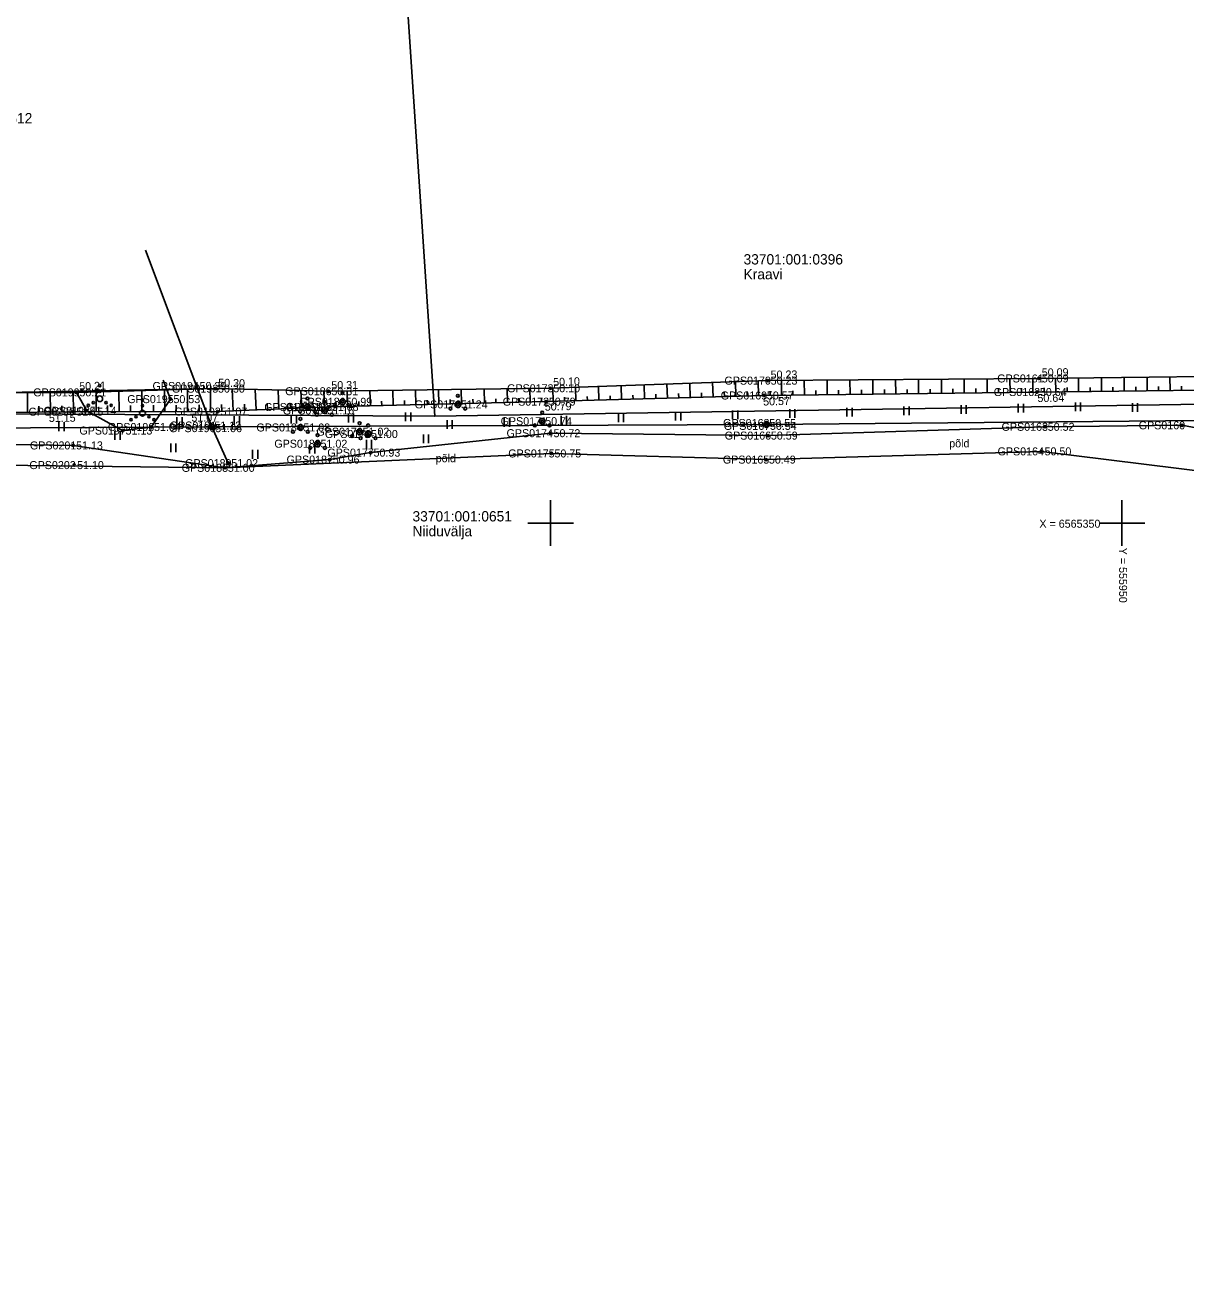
# Model space of a CAD drawing. Extents: x 551623 to 559850, y 6561220 to 6567135.
# Drawn here: x 555854 to 555955.5, y 6565284.2 to 6565393.6 of the extents above; entities that cross this region are included whole.
import ezdxf

# ---------------------------------------------------------------- set-up
doc = ezdxf.new("R2010")
doc.units = 0
for name, color, linetype in [('HALJASTUS', 7, 'Continuous'), ('KORGUS-EH2000', 7, 'Continuous'), ('KPOHULIIN', 7, 'Continuous'), ('MOOTKORG-EH2000', 7, 'Continuous'), ('MOOTMPUNKT', 7, 'Continuous'), ('MOOTNR', 7, 'Continuous'), ('MOOTPIIR', 7, 'Continuous'), ('MPOHULIIN', 7, 'Continuous'), ('PIIR', 7, 'Continuous'), ('POST', 7, 'Continuous'), ('PUU', 7, 'Continuous'), ('RELJEEF', 7, 'Continuous'), ('VORK', 7, 'Continuous')]:
    doc.layers.add(name, color=color, linetype=linetype)

msp = doc.modelspace()

# ---------------------------------------------------------------- linework, layer by layer
at = {"layer": 'HALJASTUS'}
for p, q in [((555930.93, 6565360.19), (555930.93, 6565359.43)), ((555931.39, 6565360.19), (555931.39, 6565359.43)), ((555935.93, 6565360.31), (555935.93, 6565359.55)), ((555936.38, 6565360.31), (555936.38, 6565359.55)), ((555940.93, 6565360.43), (555940.93, 6565359.67)), ((555941.38, 6565360.43), (555941.38, 6565359.67)), ((555945.93, 6565360.55), (555945.93, 6565359.78)), ((555946.38, 6565360.55), (555946.38, 6565359.78)), ((555950.92, 6565360.5), (555950.92, 6565359.74)), ((555951.37, 6565360.5), (555951.37, 6565359.74)), ((555867.31, 6565359.25), (555867.31, 6565358.49)), ((555867.77, 6565359.25), (555867.77, 6565358.49)), ((555872.31, 6565359.35), (555872.31, 6565358.59)), ((555872.77, 6565359.35), (555872.77, 6565358.59)), ((555877.31, 6565359.46), (555877.31, 6565358.7)), ((555877.77, 6565359.46), (555877.77, 6565358.7)), ((555882.31, 6565359.57), (555882.31, 6565358.8)), ((555882.76, 6565359.57), (555882.76, 6565358.8)), ((555887.31, 6565359.67), (555887.31, 6565358.91)), ((555887.76, 6565359.67), (555887.76, 6565358.91)), ((555895.95, 6565359.19), (555895.95, 6565358.43)), ((555896.4, 6565359.19), (555896.4, 6565358.43)), ((555900.94, 6565359.39), (555900.94, 6565358.63)), ((555901.4, 6565359.39), (555901.4, 6565358.63)), ((555905.94, 6565359.58), (555905.94, 6565358.82)), ((555906.39, 6565359.58), (555906.39, 6565358.82)), ((555910.94, 6565359.72), (555910.94, 6565358.96)), ((555911.39, 6565359.72), (555911.39, 6565358.96)), ((555915.93, 6565359.84), (555915.93, 6565359.08)), ((555916.39, 6565359.84), (555916.39, 6565359.08)), ((555920.93, 6565359.96), (555920.93, 6565359.19)), ((555921.39, 6565359.96), (555921.39, 6565359.19)), ((555925.93, 6565360.07), (555925.93, 6565359.31)), ((555926.39, 6565360.07), (555926.39, 6565359.31)), ((555856.97, 6565358.82), (555856.97, 6565358.05)), ((555857.43, 6565358.82), (555857.43, 6565358.05)), ((555861.88, 6565358.03), (555861.88, 6565357.27)), ((555862.33, 6565358.03), (555862.33, 6565357.27)), ((555890.95, 6565359), (555890.95, 6565358.23)), ((555891.4, 6565359), (555891.4, 6565358.23)), ((555866.76, 6565356.97), (555866.76, 6565356.2)), ((555867.21, 6565356.97), (555867.21, 6565356.2)), ((555878.91, 6565356.84), (555878.91, 6565356.08)), ((555879.36, 6565356.84), (555879.36, 6565356.08)), ((555883.89, 6565357.29), (555883.89, 6565356.53)), ((555884.34, 6565357.29), (555884.34, 6565356.53)), ((555888.87, 6565357.75), (555888.87, 6565356.98)), ((555889.32, 6565357.75), (555889.32, 6565356.98)), ((555873.93, 6565356.39), (555873.93, 6565355.63)), ((555874.38, 6565356.39), (555874.38, 6565355.63))]:
    msp.add_line(p, q, dxfattribs=at)
for points in [[(555858.51, 6565361.42), (555859.41, 6565359.82), (555862.55, 6565358.09), (555865.04, 6565358.4), (555866.74, 6565360.84), (555866.1, 6565362.51)], [(555785.42, 6565354.5), (555797.66, 6565356.6), (555822.01, 6565356.17), (555839.03, 6565357.1), (555858.22, 6565356.79), (555871.5, 6565354.83), (555880.68, 6565355.55), (555884.25, 6565356.16), (555900, 6565357.86), (555919.02, 6565357.65), (555943.25, 6565358.42), (555955.25, 6565358.55), (555967.13, 6565356.34), (555981.6, 6565352.01), (555991.48, 6565347.29)]]:
    msp.add_lwpolyline(points, dxfattribs=at)
for centre, radius in [((555860.55, 6565362.02), 0.1), ((555860.55, 6565361.52), 0.1), ((555859.55, 6565360.29), 0.1), ((555859.98, 6565360.54), 0.1), ((555860.55, 6565360.87), 0.25), ((555861.11, 6565360.54), 0.1), ((555861.55, 6565360.29), 0.1), ((555864.29, 6565360.76), 0.1), ((555864.29, 6565360.26), 0.1), ((555863.29, 6565359.04), 0.1), ((555863.73, 6565359.29), 0.1), ((555864.29, 6565359.61), 0.25), ((555864.86, 6565359.29), 0.1), ((555865.29, 6565359.04), 0.1)]:
    msp.add_circle(centre, radius, dxfattribs=at)
at = {"layer": 'KORGUS-EH2000'}
for centre in [(555919, 6565362.46), (555942.73, 6565362.65), (555858.51, 6565361.42), (555870.64, 6565361.76), (555880.56, 6565361.53), (555899.98, 6565361.79), (555918.67, 6565361.16), (555942.56, 6565361.46), (555880.6, 6565360.16), (555899.59, 6565360.62), (555858.24, 6565359.74), (555870.86, 6565359.75), (555943.25, 6565358.42), (555955.25, 6565358.55), (555858.22, 6565356.79), (555919.02, 6565357.65), (555884.25, 6565356.16), (555900.08, 6565356.09), (555942.97, 6565356.27), (555858.31, 6565355.07), (555871.5, 6565354.83), (555880.68, 6565355.55), (555918.85, 6565355.55)]:
    msp.add_circle(centre, 0.1, dxfattribs=at)
at = {"layer": 'KPOHULIIN'}
msp.add_lwpolyline([(555766.29, 6565358.13), (555774.48, 6565357.81), (555774.48, 6565357.81), (555822.76, 6565358.14), (555870.36, 6565358.42), (555918.91, 6565358.62), (555918.91, 6565358.62), (555966.51, 6565359.06), (556012.01, 6565359.61), (556063.1, 6565345.17), (556063.1, 6565345.17), (556112.63, 6565331.11), (556160.57, 6565309.95), (556211.02, 6565287.53)], dxfattribs=at)
at = {"layer": 'MOOTMPUNKT'}
for centre in [(555919, 6565362.46), (555942.73, 6565362.65), (555858.51, 6565361.42), (555869.02, 6565361.99), (555870.64, 6565361.76), (555880.56, 6565361.53), (555899.98, 6565361.79), (555918.67, 6565361.16), (555942.56, 6565361.46), (555866.74, 6565360.84), (555878.73, 6565360.15), (555880.6, 6565360.16), (555881.79, 6565360.61), (555891.89, 6565360.38), (555899.59, 6565360.62), (555858.24, 6565359.74), (555859.41, 6565359.82), (555870.86, 6565359.75), (555880.21, 6565359.85), (555862.55, 6565358.09), (555865.04, 6565358.4), (555870.32, 6565358.53), (555870.4, 6565358.3), (555878.11, 6565358.36), (555883.29, 6565357.99), (555899.27, 6565358.91), (555900, 6565357.86), (555918.88, 6565358.75), (555918.94, 6565358.5), (555943.25, 6565358.42), (555955.25, 6565358.55), (555858.22, 6565356.79), (555879.61, 6565356.94), (555884.03, 6565357.79), (555919.02, 6565357.65), (555884.25, 6565356.16), (555900.08, 6565356.09), (555942.97, 6565356.27), (555858.31, 6565355.07), (555871.5, 6565354.83), (555871.8, 6565355.24), (555880.68, 6565355.55), (555918.85, 6565355.55)]:
    msp.add_circle(centre, 0.1, dxfattribs=at)
at = {"layer": 'MOOTPIIR'}
for points in [[(556057.93, 6565353.82), (556039.2, 6565356.19), (556028.75, 6565357.94), (556026.17, 6565358.36), (556019.77, 6565359.21), (556019.9, 6565364.75), (556021.56, 6565374.26), (556015.15, 6565374.33), (556012.73, 6565375.39), (555993.91, 6565375.82), (555986.51, 6565374.87), (555981.26, 6565364.2), (555966.86, 6565362.93), (555942.73, 6565362.65), (555919, 6565362.46), (555899.98, 6565361.79), (555880.56, 6565361.53), (555870.64, 6565361.76), (555852.22, 6565361.42)], [(555839.44, 6565355.22), (555871.5, 6565354.83), (555900.08, 6565356.09), (555918.85, 6565355.55), (555942.97, 6565356.27), (555966.76, 6565353.3), (555985.37, 6565350.61), (555996.73, 6565349.22), (556009.02, 6565348.03), (556019.67, 6565346.94), (556026.62, 6565346.44), (556031.51, 6565345.23), (556038.74, 6565344.78), (556063.16, 6565343.59)]]:
    msp.add_lwpolyline(points, dxfattribs=at)
at = {"layer": 'MPOHULIIN'}
for points in [[(555864.55, 6565373.87), (555870.36, 6565358.42)], [(555774.48, 6565357.81), (555822.76, 6565358.14), (555822.76, 6565358.14), (555870.36, 6565358.42)]]:
    msp.add_lwpolyline(points, dxfattribs=at)
at = {"layer": 'PIIR'}
for points in [[(555860.69, 6565787.05), (556134.83, 6565867.67), (556136.76, 6565868.24), (556138.68, 6565868.81), (556304.72, 6565917.64), (556407.28, 6565947.65), (556409.2, 6565948.21), (556411.12, 6565948.77), (556555.39, 6565990.98), (556602.55, 6565855.41), (556340.11, 6565662.55), (556145.23, 6565518.55), (556122.95, 6565328.71), (556065.95, 6565349.3), (555986.85, 6565360.88), (555889.86, 6565359.34), (555877.35, 6565546.73)], [(555823.05, 6565554.69), (555877.35, 6565546.73), (555889.86, 6565359.34), (555792.17, 6565359.86)], [(555766.77, 6565362.31), (555785.15, 6565359.9), (555792.17, 6565359.86), (555889.86, 6565359.34), (555986.85, 6565360.88), (556065.95, 6565349.3), (556122.95, 6565328.71), (556199.38, 6565295.85), (556198.85, 6565282.81), (556195.83, 6565275.41), (556189.32, 6565262.35), (556176.88, 6565235.57), (556133.25, 6565139.15), (556097.67, 6565060.64), (555982.17, 6564796.57), (555965.54, 6564731.83), (555935.2, 6564801.96), (555871.92, 6565015.39), (555870.22, 6565021.13), (555867.36, 6565030.76)]]:
    msp.add_lwpolyline(points, close=True, dxfattribs=at)
at = {"layer": 'POST'}
msp.add_lwpolyline([(555870.36, 6565358.42), (555871.8, 6565355.24)], dxfattribs=at)
for centre, radius in [((555870.36, 6565358.42), 0.25), ((555918.91, 6565358.62), 0.25), ((555871.8, 6565355.24), 0.125), ((555871.8, 6565355.24), 0.105), ((555871.8, 6565355.24), 0.0851), ((555871.8, 6565355.24), 0.0651), ((555871.8, 6565355.24), 0.0451), ((555871.8, 6565355.24), 0.0251), ((555871.8, 6565355.24), 0.00511)]:
    msp.add_circle(centre, radius, dxfattribs=at)
at = {"layer": 'PUU'}
for centre, radius in [((555881.79, 6565361.36), 0.125), ((555891.89, 6565361.13), 0.125), ((555878.73, 6565360.15), 0.25), ((555878.73, 6565360.9), 0.125), ((555880.21, 6565360.6), 0.125), ((555881.14, 6565360.23), 0.125), ((555881.79, 6565360.61), 0.25), ((555882.44, 6565360.23), 0.125), ((555891.24, 6565360.01), 0.125), ((555891.89, 6565360.38), 0.25), ((555892.54, 6565360.01), 0.125), ((555878.08, 6565359.78), 0.125), ((555878.11, 6565359.11), 0.125), ((555879.38, 6565359.78), 0.125), ((555879.56, 6565359.48), 0.125), ((555880.21, 6565359.85), 0.25), ((555880.86, 6565359.48), 0.125), ((555899.27, 6565358.91), 0.25), ((555899.27, 6565359.66), 0.125), ((555877.46, 6565357.99), 0.125), ((555878.11, 6565358.36), 0.25), ((555878.76, 6565357.99), 0.125), ((555883.29, 6565357.99), 0.25), ((555883.29, 6565358.74), 0.125), ((555884.03, 6565357.79), 0.25), ((555884.03, 6565358.54), 0.125), ((555898.62, 6565358.54), 0.125), ((555899.92, 6565358.54), 0.125), ((555879.61, 6565356.94), 0.25), ((555879.61, 6565357.69), 0.125), ((555882.64, 6565357.61), 0.125), ((555883.38, 6565357.42), 0.125), ((555883.94, 6565357.61), 0.125), ((555884.68, 6565357.42), 0.125), ((555878.96, 6565356.57), 0.125), ((555880.26, 6565356.57), 0.125)]:
    msp.add_circle(centre, radius, dxfattribs=at)
at = {"layer": 'RELJEEF'}
for p, q in [((555916.21, 6565361.09), (555916.18, 6565362.36)), ((555918.21, 6565361.14), (555918.18, 6565362.43)), ((555920.21, 6565361.18), (555920.2, 6565362.47)), ((555922.21, 6565361.2), (555922.2, 6565362.48)), ((555924.21, 6565361.23), (555924.2, 6565362.5)), ((555926.21, 6565361.25), (555926.2, 6565362.52)), ((555928.21, 6565361.28), (555928.2, 6565362.53)), ((555930.21, 6565361.3), (555930.2, 6565362.55)), ((555932.21, 6565361.33), (555932.2, 6565362.56)), ((555934.21, 6565361.35), (555934.2, 6565362.58)), ((555936.21, 6565361.38), (555936.2, 6565362.59)), ((555938.21, 6565361.41), (555938.2, 6565362.61)), ((555940.21, 6565361.43), (555940.2, 6565362.63)), ((555942.21, 6565361.46), (555942.2, 6565362.64)), ((555944.21, 6565361.48), (555944.2, 6565362.66)), ((555946.21, 6565361.5), (555946.2, 6565362.69)), ((555948.21, 6565361.53), (555948.2, 6565362.71)), ((555950.21, 6565361.55), (555950.2, 6565362.73)), ((555952.21, 6565361.57), (555952.2, 6565362.76)), ((555954.21, 6565361.6), (555954.2, 6565362.78)), ((555854.24, 6565359.7), (555854.22, 6565361.42)), ((555856.24, 6565359.72), (555856.22, 6565361.42)), ((555858.24, 6565359.74), (555858.22, 6565361.42)), ((555860.24, 6565359.74), (555860.23, 6565361.47)), ((555862.24, 6565359.74), (555862.23, 6565361.53)), ((555864.24, 6565359.74), (555864.23, 6565361.59)), ((555866.24, 6565359.74), (555866.23, 6565361.64)), ((555868.24, 6565359.74), (555868.23, 6565361.7)), ((555870.24, 6565359.75), (555870.23, 6565361.75)), ((555872.23, 6565359.81), (555872.15, 6565361.73)), ((555874.23, 6565359.89), (555874.16, 6565361.68)), ((555876.23, 6565359.98), (555876.16, 6565361.63)), ((555878.23, 6565360.06), (555878.16, 6565361.58)), ((555880.23, 6565360.15), (555880.17, 6565361.54)), ((555882.23, 6565360.2), (555882.19, 6565361.55)), ((555884.23, 6565360.25), (555884.19, 6565361.58)), ((555886.22, 6565360.3), (555886.19, 6565361.6)), ((555888.22, 6565360.35), (555888.19, 6565361.63)), ((555890.22, 6565360.4), (555890.19, 6565361.66)), ((555892.22, 6565360.45), (555892.19, 6565361.69)), ((555894.22, 6565360.49), (555894.19, 6565361.71)), ((555896.22, 6565360.54), (555896.19, 6565361.74)), ((555898.22, 6565360.59), (555898.19, 6565361.77)), ((555900.22, 6565360.64), (555900.19, 6565361.8)), ((555902.22, 6565360.7), (555902.19, 6565361.87)), ((555904.22, 6565360.75), (555904.19, 6565361.94)), ((555906.22, 6565360.81), (555906.18, 6565362.01)), ((555908.22, 6565360.86), (555908.18, 6565362.08)), ((555909.22, 6565360.89), (555909.21, 6565361.26)), ((555910.22, 6565360.92), (555910.18, 6565362.15)), ((555911.22, 6565360.95), (555911.21, 6565361.32)), ((555912.22, 6565360.98), (555912.18, 6565362.22)), ((555913.22, 6565361), (555913.21, 6565361.38)), ((555914.22, 6565361.03), (555914.18, 6565362.29)), ((555915.21, 6565361.06), (555915.2, 6565361.44)), ((555917.21, 6565361.12), (555917.2, 6565361.5)), ((555919.21, 6565361.16), (555919.21, 6565361.55)), ((555921.21, 6565361.19), (555921.21, 6565361.58)), ((555923.21, 6565361.22), (555923.21, 6565361.6)), ((555925.21, 6565361.24), (555925.21, 6565361.62)), ((555927.21, 6565361.27), (555927.21, 6565361.64)), ((555929.21, 6565361.29), (555929.21, 6565361.67)), ((555931.21, 6565361.32), (555931.21, 6565361.69)), ((555933.21, 6565361.34), (555933.21, 6565361.71)), ((555935.21, 6565361.37), (555935.21, 6565361.73)), ((555937.21, 6565361.39), (555937.21, 6565361.76)), ((555939.21, 6565361.42), (555939.21, 6565361.78)), ((555941.21, 6565361.44), (555941.21, 6565361.8)), ((555943.21, 6565361.47), (555943.21, 6565361.82)), ((555945.21, 6565361.49), (555945.21, 6565361.85)), ((555947.21, 6565361.52), (555947.21, 6565361.87)), ((555949.21, 6565361.54), (555949.21, 6565361.89)), ((555951.21, 6565361.56), (555951.21, 6565361.92)), ((555953.21, 6565361.59), (555953.21, 6565361.94)), ((555955.21, 6565361.61), (555955.21, 6565361.96)), ((555855.24, 6565359.71), (555855.23, 6565360.22)), ((555857.24, 6565359.73), (555857.23, 6565360.24)), ((555859.24, 6565359.74), (555859.24, 6565360.25)), ((555861.24, 6565359.74), (555861.24, 6565360.27)), ((555863.24, 6565359.74), (555863.24, 6565360.29)), ((555865.24, 6565359.74), (555865.24, 6565360.3)), ((555867.24, 6565359.74), (555867.24, 6565360.32)), ((555869.24, 6565359.75), (555869.24, 6565360.34)), ((555871.24, 6565359.76), (555871.21, 6565360.36)), ((555873.23, 6565359.85), (555873.21, 6565360.4)), ((555875.23, 6565359.93), (555875.21, 6565360.45)), ((555877.23, 6565360.02), (555877.21, 6565360.5)), ((555879.23, 6565360.1), (555879.21, 6565360.54)), ((555881.23, 6565360.18), (555881.22, 6565360.59)), ((555883.23, 6565360.23), (555883.22, 6565360.63)), ((555885.23, 6565360.28), (555885.22, 6565360.67)), ((555887.22, 6565360.32), (555887.22, 6565360.71)), ((555889.22, 6565360.37), (555889.21, 6565360.75)), ((555891.22, 6565360.42), (555891.21, 6565360.8)), ((555893.22, 6565360.47), (555893.21, 6565360.84)), ((555895.22, 6565360.52), (555895.21, 6565360.88)), ((555897.22, 6565360.57), (555897.21, 6565360.92)), ((555899.22, 6565360.61), (555899.21, 6565360.96)), ((555901.22, 6565360.67), (555901.21, 6565361.02)), ((555903.22, 6565360.73), (555903.21, 6565361.08)), ((555905.22, 6565360.78), (555905.21, 6565361.14)), ((555907.22, 6565360.84), (555907.21, 6565361.2))]:
    msp.add_line(p, q, dxfattribs=at)
for points in [[(555977.43, 6565364.06), (555981.26, 6565364.2), (555982.4, 6565363.02), (555981.07, 6565362.02), (555966.44, 6565361.74), (555942.56, 6565361.46), (555918.67, 6565361.16), (555899.59, 6565360.62), (555880.6, 6565360.16), (555870.86, 6565359.75), (555858.24, 6565359.74), (555839.06, 6565359.56), (555820.21, 6565359.55), (555797.76, 6565359.99), (555784.55, 6565360.47), (555784.14, 6565361.85), (555784.79, 6565363.46), (555797.78, 6565363.82), (555819.88, 6565363.91), (555838.74, 6565363.56), (555851.24, 6565363.43)], [(555785.17, 6565362.24), (555796.74, 6565361.82), (555819.94, 6565361.44), (555839.06, 6565361.41), (555858.51, 6565361.42), (555870.64, 6565361.76), (555880.56, 6565361.53), (555899.98, 6565361.79), (555919, 6565362.46), (555942.73, 6565362.65), (555966.86, 6565362.93), (555982.4, 6565363.02)]]:
    msp.add_lwpolyline(points, dxfattribs=at)
at = {"layer": 'VORK'}
for p, q in [((555900, 6565352), (555900, 6565348)), ((555950, 6565352), (555950, 6565348)), ((555898, 6565350), (555902, 6565350)), ((555948, 6565350), (555952, 6565350))]:
    msp.add_line(p, q, dxfattribs=at)

# ---------------------------------------------------------------- texts
at = {"layer": 'HALJASTUS'}
for p in [(555934.89, 6565356.62), (555889.95, 6565355.32)]:
    msp.add_text('põld', height=0.7, dxfattribs=at).set_placement(p)
at = {"layer": 'KORGUS-EH2000'}
for s, rotation, p in [(' 50.09', 0.6631, (555942.73, 6565362.82)), (' 50.21', 1.6017, (555858.5, 6565361.6)), (' 50.30', 358.633, (555870.65, 6565361.94)), (' 50.31', 0.784, (555880.56, 6565361.7)), (' 50.10', 2.0056, (555899.98, 6565361.97)), (' 50.23', 0.4514, (555919, 6565362.63)), (' 50.64', 0.726, (555942.35, 6565360.58)), (' 50.79', 1.3869, (555899.24, 6565359.82)), (' 50.57', 1.6036, (555918.35, 6565360.27)), (' 51.15', 0.5372, (555855.84, 6565358.84)), (' 51.07', 0.03, (555868.31, 6565358.87))]:
    msp.add_text(s, height=0.7, rotation=rotation, dxfattribs=at).set_placement(p)
for s, p in [(' 51.16', (555880.21, 6565359.5)), (' 50.59', (555919.02, 6565357.3)), (' 50.52', (555943.25, 6565358.07)), (' 51.13', (555858.22, 6565356.44)), (' 50.96', (555880.68, 6565355.2)), (' 50.93', (555884.25, 6565355.81)), (' 50.75', (555900.08, 6565355.74)), (' 50.49', (555918.85, 6565355.2)), (' 50.50', (555942.97, 6565355.92)), (' 51.10', (555858.31, 6565354.72)), (' 51.00', (555871.5, 6565354.48))]:
    msp.add_text(s, height=0.7, dxfattribs=at).set_placement(p)
at = {"layer": 'MOOTKORG-EH2000'}
for s, p in [(' 50.39', (555869.02, 6565361.64)), (' 50.23', (555919, 6565362.11)), (' 50.09', (555942.73, 6565362.3)), (' 50.21', (555858.51, 6565361.08)), (' 50.30', (555870.64, 6565361.41)), (' 50.31', (555880.56, 6565361.18)), (' 50.10', (555899.98, 6565361.44)), (' 50.57', (555918.67, 6565360.81)), (' 50.64', (555942.56, 6565361.11)), (' 51.14', (555859.41, 6565359.47)), (' 50.53', (555866.74, 6565360.49)), (' 51.27', (555878.73, 6565359.8)), (' 51.16', (555880.21, 6565359.5)), (' 51.08', (555880.6, 6565359.81)), (' 50.99', (555881.79, 6565360.26)), (' 51.24', (555891.89, 6565360.03)), (' 50.79', (555899.59, 6565360.27)), (' 51.15', (555858.24, 6565359.39)), (' 51.07', (555870.86, 6565359.4)), (' 50.74', (555899.27, 6565358.56)), (' 50.55', (555918.88, 6565358.4)), (' 51.13', (555862.55, 6565357.74)), (' 51.04', (555865.04, 6565358.05)), (' 51.12', (555870.32, 6565358.18)), (' 51.06', (555870.4, 6565357.95)), (' 51.08', (555878.11, 6565358.01)), (' 51.02', (555883.29, 6565357.64)), (' 51.00', (555884.03, 6565357.44)), (' 50.72', (555900, 6565357.51)), (' 50.54', (555918.94, 6565358.15)), (' 50.59', (555919.02, 6565357.3)), (' 50.52', (555943.25, 6565358.07)), (' 51.13', (555858.22, 6565356.44)), (' 51.02', (555879.61, 6565356.59)), (' 50.96', (555880.68, 6565355.2)), (' 50.93', (555884.25, 6565355.81)), (' 50.75', (555900.08, 6565355.74)), (' 50.49', (555918.85, 6565355.2)), (' 50.50', (555942.97, 6565355.92)), (' 51.10', (555858.31, 6565354.72)), (' 51.00', (555871.5, 6565354.48)), (' 51.02', (555871.8, 6565354.89))]:
    msp.add_text(s, height=0.7, dxfattribs=at).set_placement(p)
at = {"layer": 'MOOTNR'}
for s, p in [('GPS0194 ', (555865.17, 6565361.64)), ('GPS0170 ', (555915.22, 6565362.11)), ('GPS0161 ', (555939.09, 6565362.3)), ('GPS0199 ', (555854.73, 6565361.08)), ('GPS0193 ', (555866.86, 6565361.41)), ('GPS0186 ', (555876.78, 6565361.18)), ('GPS0173 ', (555896.2, 6565361.44)), ('GPS0169 ', (555914.89, 6565360.81)), ('GPS0162 ', (555938.78, 6565361.11)), ('GPS0198 ', (555855.63, 6565359.47)), ('GPS0195 ', (555862.96, 6565360.49)), ('GPS0182 ', (555874.95, 6565359.8)), ('GPS0181 ', (555876.57, 6565359.5)), ('GPS0185 ', (555876.82, 6565359.81)), ('GPS0180 ', (555878.01, 6565360.26)), ('GPS0176 ', (555888.11, 6565360.03)), ('GPS0172 ', (555895.81, 6565360.27)), ('GPS0200 ', (555854.32, 6565359.39)), ('GPS0192 ', (555867.08, 6565359.4)), ('GPS0171 ', (555895.63, 6565358.56)), ('GPS0168 ', (555915.1, 6565358.4)), ('GPS0197 ', (555858.77, 6565357.74)), ('GPS0196 ', (555861.26, 6565358.05)), ('GPS0190 ', (555866.62, 6565357.95)), ('GPS0191 ', (555866.68, 6565358.18)), ('GPS0184 ', (555874.26, 6565358.01)), ('GPS0179 ', (555879.51, 6565357.64)), ('GPS0178 ', (555880.25, 6565357.44)), ('GPS0174 ', (555896.15, 6565357.51)), ('GPS0167 ', (555915.16, 6565358.15)), ('GPS0166 ', (555915.24, 6565357.3)), ('GPS0163 ', (555939.47, 6565358.07)), ('GPS0160 ', (555951.47, 6565358.2)), ('GPS0201 ', (555854.44, 6565356.44)), ('GPS0183 ', (555875.83, 6565356.59)), ('GPS0187 ', (555876.9, 6565355.2)), ('GPS0177 ', (555880.47, 6565355.81)), ('GPS0175 ', (555896.3, 6565355.74)), ('GPS0165 ', (555915.08, 6565355.2)), ('GPS0164 ', (555939.12, 6565355.92)), ('GPS0202 ', (555854.39, 6565354.72)), ('GPS0188 ', (555867.72, 6565354.48)), ('GPS0189 ', (555868.02, 6565354.89))]:
    msp.add_text(s, height=0.7, dxfattribs=at).set_placement(p)
at = {"layer": 'PIIR'}
for s, p in [('33701:001:0512', (555845.95, 6565384.97)), ('33701:001:0396', (555916.89, 6565372.62)), ('Kraavi', (555916.89, 6565371.32)), ('33701:001:0651', (555887.92, 6565350.14)), ('Niiduvälja', (555887.92, 6565348.84))]:
    msp.add_text(s, height=0.9, dxfattribs=at).set_placement(p)
at = {"layer": 'VORK'}
msp.add_text('X = 6565350', height=0.7, dxfattribs=at).set_placement((555942.78, 6565349.59))
msp.add_text('Y = 555950 ', height=0.7, rotation=270, dxfattribs=at).set_placement((555949.75, 6565347.84))

doc.saveas('drawing.dxf')
